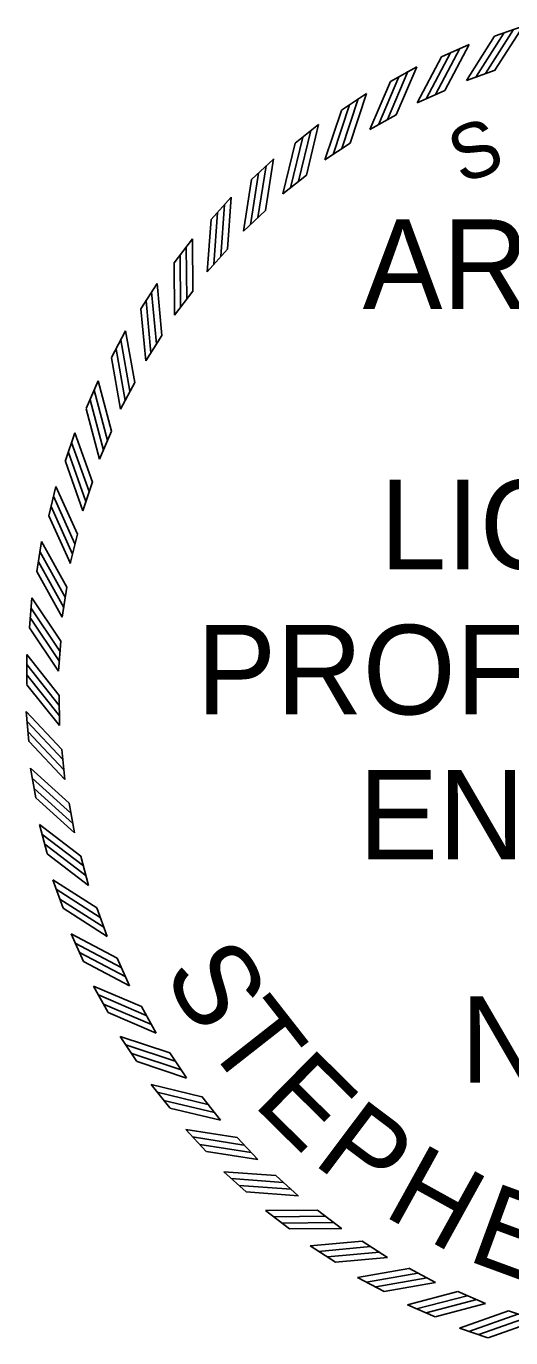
# Model space of a CAD drawing. Extents: x 16 to 1228740, y 11 to 152440.
# Drawn here: x 17.6868 to 17.7474, y 10.8193 to 10.9832 of the extents above; entities that cross this region are included whole.
import ezdxf

# ---------------------------------------------------------------- set-up
doc = ezdxf.new("R2010")
doc.units = 0
doc.layers.add('STAMP_FRED', color=7, linetype='Continuous')

msp = doc.modelspace()

# ---------------------------------------------------------------- linework, layer by layer
at = {"layer": 'STAMP_FRED'}
for p, q in [((17.74533, 10.98191), (17.74888, 10.98317)), ((17.7387, 10.97936), (17.74214, 10.98091)), ((17.7323, 10.97627), (17.7356, 10.9781)), ((17.74182, 10.97641), (17.74538, 10.97767)), ((17.73565, 10.97359), (17.7391, 10.97514)), ((17.72617, 10.97267), (17.72931, 10.97476)), ((17.72974, 10.97027), (17.73304, 10.9721)), ((17.72037, 10.96857), (17.72332, 10.97091)), ((17.72412, 10.96648), (17.72726, 10.96857)), ((17.71492, 10.964), (17.71767, 10.96658)), ((17.71883, 10.96223), (17.72179, 10.96458)), ((17.70987, 10.959), (17.7124, 10.9618)), ((17.71391, 10.95756), (17.71667, 10.96014)), ((17.70525, 10.9536), (17.70754, 10.9566)), ((17.7094, 10.9525), (17.71193, 10.9553)), ((17.70109, 10.94784), (17.70313, 10.95102)), ((17.70532, 10.94708), (17.70761, 10.95008)), ((17.69743, 10.94176), (17.69919, 10.94509)), ((17.7017, 10.94135), (17.70374, 10.94453)), ((17.69427, 10.93539), (17.69575, 10.93885)), ((17.69856, 10.93533), (17.70033, 10.93867)), ((17.69165, 10.92878), (17.69285, 10.93236)), ((17.69594, 10.92908), (17.69742, 10.93255)), ((17.68959, 10.92198), (17.69048, 10.92564)), ((17.69384, 10.92263), (17.69503, 10.92622)), ((17.69227, 10.91603), (17.69317, 10.91971)), ((17.6881, 10.91503), (17.68868, 10.91876)), ((17.69126, 10.90933), (17.69185, 10.91306)), ((17.68718, 10.90799), (17.68746, 10.91175)), ((17.69081, 10.90256), (17.69108, 10.90633)), ((17.68685, 10.90089), (17.68682, 10.90466)), ((17.69091, 10.89578), (17.69088, 10.89956)), ((17.68711, 10.89379), (17.68677, 10.89754)), ((17.69158, 10.88903), (17.69123, 10.89279)), ((17.68795, 10.88673), (17.6873, 10.89044)), ((17.6928, 10.88236), (17.69214, 10.88608)), ((17.68938, 10.87977), (17.68842, 10.88341)), ((17.69457, 10.87581), (17.6936, 10.87947)), ((17.69137, 10.87295), (17.69011, 10.8765)), ((17.69687, 10.86943), (17.69561, 10.873)), ((17.69392, 10.86631), (17.69237, 10.86975)), ((17.69969, 10.86327), (17.69814, 10.86671)), ((17.69701, 10.85991), (17.69518, 10.86321)), ((17.70301, 10.85735), (17.70118, 10.86066)), ((17.70061, 10.85379), (17.69852, 10.85693)), ((17.70681, 10.85174), (17.70471, 10.85488)), ((17.70471, 10.84799), (17.70237, 10.85094)), ((17.71105, 10.84645), (17.70871, 10.84941)), ((17.70928, 10.84254), (17.7067, 10.84529)), ((17.71572, 10.84153), (17.71314, 10.84429)), ((17.71428, 10.83749), (17.71148, 10.84002)), ((17.72078, 10.83702), (17.71798, 10.83955)), ((17.71968, 10.83287), (17.71668, 10.83516)), ((17.7262, 10.83294), (17.7232, 10.83523)), ((17.72544, 10.82871), (17.72226, 10.83074)), ((17.73193, 10.82932), (17.72875, 10.83135)), ((17.73795, 10.82618), (17.73461, 10.82795)), ((17.73153, 10.82504), (17.72819, 10.82681)), ((17.7442, 10.82355), (17.74073, 10.82504)), ((17.73789, 10.82189), (17.73443, 10.82337)), ((17.75065, 10.82145), (17.74706, 10.82265)), ((17.7445, 10.81927), (17.74092, 10.82046))]:
    msp.add_line(p, q, dxfattribs=at)
for points in [[(17.74537, 10.97768), (17.74889, 10.98317)], [(17.74181, 10.97641), (17.74533, 10.98191)], [(17.74296, 10.9768), (17.74647, 10.9823)], [(17.74419, 10.97727), (17.7477, 10.98276)], [(17.73676, 10.97408), (17.7398, 10.97984)], [(17.73794, 10.97464), (17.74099, 10.98041)], [(17.73909, 10.97514), (17.74214, 10.98091)], [(17.73304, 10.9721), (17.7356, 10.9781)], [(17.73565, 10.97359), (17.73869, 10.97936)], [(17.7308, 10.97085), (17.73336, 10.97685)], [(17.73193, 10.97151), (17.73449, 10.97751)], [(17.72973, 10.97027), (17.73229, 10.97627)], [(17.72513, 10.96713), (17.72719, 10.97333)], [(17.72621, 10.96789), (17.72826, 10.97408)], [(17.72726, 10.96857), (17.72931, 10.97476)], [(17.72412, 10.96647), (17.72617, 10.97266)], [(17.7208, 10.9638), (17.72233, 10.97014)], [(17.72179, 10.96458), (17.72332, 10.97091)], [(17.71883, 10.96222), (17.72037, 10.96856)], [(17.71979, 10.96297), (17.72133, 10.96931)], [(17.71574, 10.95929), (17.71675, 10.96574)], [(17.71667, 10.96014), (17.71767, 10.96659)], [(17.71391, 10.95755), (17.71492, 10.964)], [(17.71481, 10.95837), (17.71581, 10.96482)], [(17.71193, 10.9553), (17.7124, 10.96181)], [(17.71108, 10.95438), (17.71155, 10.96088)], [(17.7094, 10.95249), (17.70987, 10.959)], [(17.71022, 10.95338), (17.71069, 10.95989)], [(17.70684, 10.94909), (17.70677, 10.95561)], [(17.70761, 10.95008), (17.70754, 10.95661)], [(17.70532, 10.94708), (17.70525, 10.9536)], [(17.70606, 10.94803), (17.706, 10.95456)], [(17.70373, 10.94453), (17.70313, 10.95102)], [(17.70236, 10.94236), (17.70176, 10.94885)], [(17.70304, 10.94348), (17.70244, 10.94997)], [(17.7017, 10.94134), (17.70109, 10.94784)], [(17.69973, 10.93757), (17.69859, 10.94399)], [(17.70033, 10.93867), (17.69919, 10.94509)], [(17.69914, 10.93639), (17.698, 10.94282)], [(17.69857, 10.93533), (17.69743, 10.94175)], [(17.69742, 10.93255), (17.69575, 10.93886)], [(17.69691, 10.9314), (17.69525, 10.93771)], [(17.69643, 10.93019), (17.69476, 10.93649)], [(17.69594, 10.92908), (17.69427, 10.93538)], [(17.69503, 10.92621), (17.69284, 10.93236)], [(17.69462, 10.92503), (17.69244, 10.93117)], [(17.69423, 10.92378), (17.69205, 10.92992)], [(17.69384, 10.92263), (17.69166, 10.92878)], [(17.69316, 10.9197), (17.69048, 10.92565)], [(17.69286, 10.91848), (17.69017, 10.92443)], [(17.69257, 10.9172), (17.68989, 10.92315)], [(17.69228, 10.91603), (17.68959, 10.92198)], [(17.69164, 10.91182), (17.68848, 10.91752)], [(17.69185, 10.91306), (17.68868, 10.91876)], [(17.69146, 10.91052), (17.6883, 10.91622)], [(17.69126, 10.90932), (17.6881, 10.91503)], [(17.69108, 10.90633), (17.68746, 10.91175)], [(17.69098, 10.90507), (17.68735, 10.9105)], [(17.69081, 10.90256), (17.68719, 10.90798)], [(17.69091, 10.90377), (17.68729, 10.90919)], [(17.69088, 10.89955), (17.68682, 10.90466)], [(17.69088, 10.8983), (17.68682, 10.90341)], [(17.69092, 10.89699), (17.68686, 10.9021)], [(17.69092, 10.89578), (17.68686, 10.90088)], [(17.69123, 10.89279), (17.68676, 10.89754)], [(17.69133, 10.89154), (17.68687, 10.89629)], [(17.69148, 10.89024), (17.68702, 10.89499)], [(17.69158, 10.88903), (17.68712, 10.89378)], [(17.69214, 10.88608), (17.6873, 10.89045)], [(17.69235, 10.88484), (17.6875, 10.88921)], [(17.6926, 10.88355), (17.68776, 10.88792)], [(17.6928, 10.88236), (17.68796, 10.88673)], [(17.6936, 10.87946), (17.68841, 10.88342)], [(17.69391, 10.87825), (17.68872, 10.8822)], [(17.69427, 10.87699), (17.68908, 10.88094)], [(17.69457, 10.87581), (17.68938, 10.87976)], [(17.69561, 10.87299), (17.69011, 10.8765)], [(17.69601, 10.8718), (17.69052, 10.87532)], [(17.69648, 10.87058), (17.69098, 10.87409)], [(17.69687, 10.86943), (17.69138, 10.87294)], [(17.69814, 10.86671), (17.69237, 10.86975)], [(17.69864, 10.86556), (17.69287, 10.8686)], [(17.69921, 10.86438), (17.69344, 10.86742)], [(17.69969, 10.86326), (17.69392, 10.86631)], [(17.70118, 10.86066), (17.69518, 10.86321)], [(17.70178, 10.85955), (17.69578, 10.86211)], [(17.70244, 10.85842), (17.69644, 10.86098)], [(17.70301, 10.85735), (17.69701, 10.85991)], [(17.70471, 10.85487), (17.69852, 10.85693)], [(17.7054, 10.85382), (17.69921, 10.85588)], [(17.70615, 10.85275), (17.69996, 10.8548)], [(17.70681, 10.85173), (17.70062, 10.85379)], [(17.70871, 10.8494), (17.70237, 10.85094)], [(17.70948, 10.84841), (17.70314, 10.84995)], [(17.71031, 10.84741), (17.70397, 10.84894)], [(17.71106, 10.84645), (17.70472, 10.84798)], [(17.71314, 10.84428), (17.7067, 10.84529)], [(17.71399, 10.84336), (17.70755, 10.84437)], [(17.71491, 10.84242), (17.70846, 10.84343)], [(17.71573, 10.84153), (17.70929, 10.84254)], [(17.71798, 10.83955), (17.71148, 10.84002)], [(17.71891, 10.83869), (17.7124, 10.83917)], [(17.7199, 10.83784), (17.71339, 10.83831)], [(17.72079, 10.83702), (17.71428, 10.83749)], [(17.7232, 10.83522), (17.71668, 10.83516)], [(17.72419, 10.83445), (17.71767, 10.83439)], [(17.72525, 10.83368), (17.71873, 10.83361)], [(17.72621, 10.83294), (17.71968, 10.83287)], [(17.72876, 10.83135), (17.72226, 10.83074)], [(17.72981, 10.83066), (17.72331, 10.83006)], [(17.73092, 10.82998), (17.72443, 10.82937)], [(17.73194, 10.82932), (17.72545, 10.82871)], [(17.73461, 10.82794), (17.72819, 10.82681)], [(17.73572, 10.82735), (17.72929, 10.82621)], [(17.73689, 10.82676), (17.73046, 10.82562)], [(17.73795, 10.82618), (17.73153, 10.82504)], [(17.74073, 10.82504), (17.73442, 10.82337)], [(17.74188, 10.82453), (17.73557, 10.82287)], [(17.7431, 10.82404), (17.73679, 10.82238)], [(17.74421, 10.82356), (17.7379, 10.82189)], [(17.74707, 10.82264), (17.74092, 10.82046)], [(17.74825, 10.82223), (17.74211, 10.82005)], [(17.74951, 10.82185), (17.74336, 10.81967)], [(17.75065, 10.82145), (17.74451, 10.81927)]]:
    msp.add_lwpolyline(points, dxfattribs=at)

# ---------------------------------------------------------------- texts
for s, height, rotation, p in [('S', 0.00686, 19.7726, (17.74115, 10.96343)), ('S', 0.01042, 300.7985, (17.70374, 10.86481)), ('T', 0.01042, 308.0945, (17.70883, 10.85628)), ('E', 0.01042, 315.3905, (17.71496, 10.84846)), ('P', 0.01042, 323.0513, (17.72241, 10.84116)), ('H', 0.01042, 331.0769, (17.73118, 10.83465)), ('E', 0.01042, 339.8321, (17.74168, 10.82902))]:
    msp.add_text(s, height=height, rotation=rotation, dxfattribs=at).set_placement(p)
for s, height, p in [('ARKANSAS', 0.011193, (17.72883, 10.94783)), ('LICENSED', 0.011193, (17.73096, 10.9153)), ('PROFESSIONAL', 0.0111934, (17.70804, 10.89717)), ('ENGINEER', 0.011193, (17.7283, 10.87905)), ('No.14501', 0.010794, (17.7411, 10.85114))]:
    msp.add_text(s, height=height, dxfattribs=at).set_placement(p)

doc.saveas('drawing.dxf')
